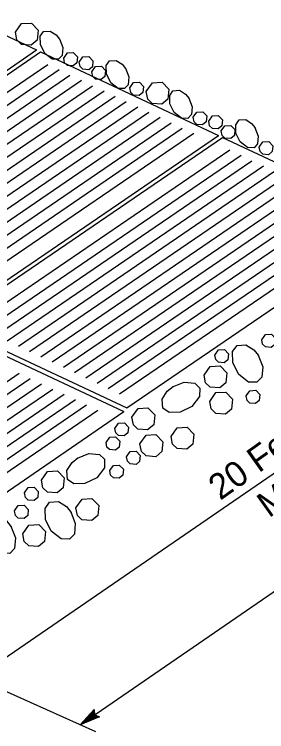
# Model space of a CAD drawing. Extents: x 6707406 to 6714471, y 1868570 to 1872341.
# Drawn here: x 6709966.5 to 6710037.9, y 1870116.6 to 1870319.2 of the extents above; entities that cross this region are included whole.
import ezdxf

# ---------------------------------------------------------------- set-up
doc = ezdxf.new("R2010")
doc.units = 0
for name, color, linetype in [('56 Stg 3 Anno', 7, 'Continuous'), ('57 Undefined', 7, 'Continuous'), ('60 Nongeo Data', 7, 'Continuous')]:
    doc.layers.add(name, color=color, linetype=linetype)

msp = doc.modelspace()

# ---------------------------------------------------------------- linework, layer by layer
at = {"layer": '56 Stg 3 Anno'}
for p, q in [((6709960.88, 1870135.33), (6710117.29, 1870242.71)), ((6709985.07, 1870118.55), (6710151.91, 1870233.1)), ((6709932.78, 1870142.01), (6709989.45, 1870116.59)), ((6709985.07, 1870118.55), (6709989.1, 1870122.86)), ((6709986.17, 1870119.31), (6709989.1, 1870122.45)), ((6709987.26, 1870120.05), (6709989.15, 1870122.08)), ((6709988.35, 1870120.8), (6709989.16, 1870121.67)), ((6709989.1, 1870122.86), (6709989.1, 1870122.86)), ((6709989.1, 1870122.86), (6709989.18, 1870121.38)), ((6709990.55, 1870120.75), (6709985.07, 1870118.55)), ((6709990.18, 1870120.92), (6709986.16, 1870119.3)), ((6709989.8, 1870121.07), (6709987.26, 1870120.05)), ((6709989.47, 1870121.25), (6709988.35, 1870120.8)), ((6709989.18, 1870121.38), (6709990.55, 1870120.75)), ((6709990.55, 1870120.75), (6709990.55, 1870120.75)), ((6709985.07, 1870118.55), (6709985.07, 1870118.55))]:
    msp.add_line(p, q, dxfattribs=at)
at = {"layer": '60 Nongeo Data'}
for p, q in [((6709933.89, 1870327.37), (6709972.77, 1870309.11)), ((6709895.36, 1870256.35), (6709972.77, 1870309.11)), ((6709896.53, 1870255.81), (6709973.94, 1870308.57)), ((6709973.94, 1870308.57), (6710024.25, 1870284.94)), ((6709903.43, 1870255.63), (6709975.95, 1870305.05)), ((6709906.61, 1870254.14), (6709979.18, 1870303.59)), ((6709909.79, 1870252.64), (6709982.23, 1870302.01)), ((6709912.98, 1870251.15), (6709985.49, 1870300.57)), ((6709916.16, 1870249.65), (6709988.6, 1870299.03)), ((6709919.34, 1870248.16), (6709991.87, 1870297.59)), ((6709922.52, 1870246.67), (6709995.05, 1870296.1)), ((6709925.7, 1870245.17), (6709998.17, 1870294.57)), ((6709928.88, 1870243.68), (6710001.39, 1870293.1)), ((6709932.06, 1870242.19), (6710004.53, 1870291.58)), ((6709935.24, 1870240.69), (6710007.74, 1870290.1)), ((6709938.43, 1870239.2), (6710010.88, 1870288.58)), ((6709941.61, 1870237.7), (6710013.99, 1870287.04)), ((6709944.79, 1870236.21), (6710017.28, 1870285.62)), ((6709946.84, 1870232.18), (6710024.25, 1870284.94)), ((6709948.01, 1870231.63), (6710025.41, 1870284.39)), ((6710025.41, 1870284.39), (6710075.72, 1870260.77)), ((6709954.91, 1870231.46), (6710027.42, 1870280.88)), ((6709958.09, 1870229.96), (6710030.66, 1870279.42)), ((6709961.27, 1870228.47), (6710033.7, 1870277.84)), ((6709964.45, 1870226.98), (6710036.97, 1870276.4)), ((6709967.63, 1870225.48), (6710040.08, 1870274.86)), ((6709970.82, 1870223.99), (6710043.34, 1870273.42)), ((6709974, 1870222.49), (6710046.53, 1870271.93)), ((6709977.18, 1870221), (6710049.65, 1870270.4)), ((6709980.36, 1870219.51), (6710052.87, 1870268.93)), ((6709983.54, 1870218.01), (6710056.01, 1870267.4)), ((6709986.72, 1870216.52), (6710059.22, 1870265.93)), ((6709989.9, 1870215.03), (6710062.35, 1870264.41)), ((6709993.08, 1870213.53), (6710065.47, 1870262.87)), ((6709996.27, 1870212.04), (6710068.76, 1870261.45)), ((6709998.31, 1870208.01), (6710075.72, 1870260.77)), ((6709948.01, 1870231.63), (6709998.31, 1870208.01)), ((6709947.18, 1870230.6), (6709997.49, 1870206.98)), ((6709895.17, 1870168.3), (6709967.84, 1870217.83)), ((6709898.35, 1870166.8), (6709971.02, 1870216.34)), ((6709901.53, 1870165.31), (6709974.21, 1870214.84)), ((6709904.71, 1870163.82), (6709977.39, 1870213.35)), ((6709907.89, 1870162.32), (6709980.57, 1870211.86)), ((6709911.07, 1870160.83), (6709983.75, 1870210.36)), ((6709914.25, 1870159.33), (6709986.93, 1870208.87)), ((6709917.44, 1870157.84), (6709990.11, 1870207.37)), ((6709919.56, 1870153.86), (6709997.49, 1870206.98))]:
    msp.add_line(p, q, dxfattribs=at)
for points in [[(6709966.8, 1870314.1), (6709968.54, 1870316.57), (6709971.31, 1870316.73), (6709973.24, 1870314.73), (6709972.96, 1870311.92), (6709971.25, 1870310.5), (6709968.51, 1870310.7), (6709967.22, 1870311.95), (6709966.8, 1870314.1)], [(6709979.24, 1870312.24), (6709980.21, 1870309.8), (6709980.01, 1870307.56), (6709979, 1870306.49), (6709977.18, 1870306.52), (6709975.11, 1870308.14), (6709973.86, 1870310.64), (6709973.82, 1870313), (6709974.76, 1870314.32), (6709976.64, 1870314.45), (6709978.32, 1870313.37), (6709979.3, 1870312.14)], [(6709980.47, 1870306.8), (6709981.51, 1870308.28), (6709983.18, 1870308.37), (6709984.34, 1870307.17), (6709984.17, 1870305.49), (6709983.14, 1870304.64), (6709981.5, 1870304.75), (6709980.72, 1870305.5), (6709980.47, 1870306.8)], [(6709984.87, 1870305.71), (6709985.91, 1870307.19), (6709987.58, 1870307.29), (6709988.74, 1870306.09), (6709988.57, 1870304.4), (6709987.54, 1870303.55), (6709985.9, 1870303.67), (6709985.12, 1870304.42), (6709984.87, 1870305.71)], [(6709997.92, 1870303.95), (6709998.88, 1870301.51), (6709998.69, 1870299.27), (6709997.68, 1870298.21), (6709995.86, 1870298.24), (6709993.79, 1870299.86), (6709992.54, 1870302.36), (6709992.5, 1870304.71), (6709993.44, 1870306.04), (6709995.32, 1870306.16), (6709997, 1870305.09), (6709997.98, 1870303.86)], [(6709988.41, 1870302.94), (6709989.46, 1870304.43), (6709991.12, 1870304.52), (6709992.28, 1870303.32), (6709992.11, 1870301.64), (6709991.08, 1870300.78), (6709989.44, 1870300.9), (6709988.67, 1870301.65), (6709988.41, 1870302.94)], [(6709999.15, 1870298.4), (6710000.19, 1870299.89), (6710001.86, 1870299.98), (6710003.02, 1870298.78), (6710002.85, 1870297.1), (6710001.82, 1870296.24), (6710000.18, 1870296.36), (6709999.4, 1870297.11), (6709999.15, 1870298.4)], [(6710003.79, 1870297.4), (6710005.53, 1870299.87), (6710008.3, 1870300.03), (6710010.23, 1870298.03), (6710009.95, 1870295.22), (6710008.24, 1870293.8), (6710005.5, 1870294), (6710004.21, 1870295.25), (6710003.79, 1870297.4)], [(6710015.85, 1870295.54), (6710016.82, 1870293.1), (6710016.62, 1870290.86), (6710015.61, 1870289.79), (6710013.79, 1870289.82), (6710011.72, 1870291.44), (6710010.47, 1870293.94), (6710010.43, 1870296.3), (6710011.37, 1870297.62), (6710013.25, 1870297.75), (6710014.93, 1870296.67), (6710015.91, 1870295.44)], [(6710017.08, 1870290.1), (6710018.12, 1870291.58), (6710019.79, 1870291.67), (6710020.95, 1870290.47), (6710020.78, 1870288.79), (6710019.75, 1870287.94), (6710018.11, 1870288.05), (6710017.33, 1870288.8), (6710017.08, 1870290.1)], [(6710021.48, 1870289.01), (6710022.53, 1870290.49), (6710024.19, 1870290.59), (6710025.35, 1870289.39), (6710025.18, 1870287.7), (6710024.15, 1870286.85), (6710022.51, 1870286.97), (6710021.73, 1870287.72), (6710021.48, 1870289.01)], [(6710025.02, 1870286.24), (6710026.07, 1870287.73), (6710027.73, 1870287.82), (6710028.89, 1870286.62), (6710028.72, 1870284.94), (6710027.69, 1870284.08), (6710026.05, 1870284.2), (6710025.28, 1870284.95), (6710025.02, 1870286.24)], [(6710034.53, 1870287.25), (6710035.5, 1870284.81), (6710035.3, 1870282.57), (6710034.29, 1870281.51), (6710032.47, 1870281.54), (6710030.4, 1870283.16), (6710029.15, 1870285.66), (6710029.11, 1870288.01), (6710030.05, 1870289.34), (6710031.93, 1870289.46), (6710033.61, 1870288.39), (6710034.59, 1870287.16)], [(6710035.76, 1870281.7), (6710036.8, 1870283.19), (6710038.47, 1870283.28), (6710039.63, 1870282.08), (6710039.46, 1870280.4), (6710038.43, 1870279.54), (6710036.79, 1870279.66), (6710036.01, 1870280.41), (6710035.76, 1870281.7)], [(6710036.48, 1870227.27), (6710037.53, 1870228.76), (6710039.19, 1870228.85), (6710040.35, 1870227.65), (6710040.18, 1870225.97), (6710039.15, 1870225.11), (6710037.51, 1870225.23), (6710036.73, 1870225.98), (6710036.48, 1870227.27)], [(6710035.45, 1870222.91), (6710036.74, 1870219.66), (6710036.48, 1870216.67), (6710035.13, 1870215.25), (6710032.7, 1870215.29), (6710029.95, 1870217.45), (6710028.28, 1870220.78), (6710028.22, 1870223.92), (6710029.48, 1870225.69), (6710031.98, 1870225.86), (6710034.22, 1870224.42), (6710035.53, 1870222.78)], [(6710023.22, 1870222.95), (6710024.27, 1870224.43), (6710025.93, 1870224.53), (6710027.09, 1870223.33), (6710026.92, 1870221.64), (6710025.89, 1870220.79), (6710024.25, 1870220.91), (6710023.48, 1870221.66), (6710023.22, 1870222.95)], [(6710020.15, 1870217.28), (6710021.89, 1870219.76), (6710024.67, 1870219.92), (6710026.6, 1870217.91), (6710026.32, 1870215.11), (6710024.6, 1870213.68), (6710021.86, 1870213.88), (6710020.57, 1870215.13), (6710020.15, 1870217.28)], [(6710011.27, 1870213.96), (6710014.52, 1870215.25), (6710017.51, 1870214.99), (6710018.93, 1870213.64), (6710018.89, 1870211.22), (6710016.73, 1870208.46), (6710013.4, 1870206.79), (6710010.26, 1870206.74), (6710008.49, 1870207.99), (6710008.32, 1870210.5), (6710009.76, 1870212.73), (6710011.4, 1870214.04)], [(6710032.06, 1870211.41), (6710033.11, 1870212.89), (6710034.77, 1870212.99), (6710035.93, 1870211.78), (6710035.76, 1870210.1), (6710034.74, 1870209.25), (6710033.09, 1870209.37), (6710032.31, 1870210.12), (6710032.06, 1870211.41)], [(6710021.79, 1870209.88), (6710023.53, 1870212.35), (6710026.3, 1870212.51), (6710028.23, 1870210.51), (6710027.95, 1870207.7), (6710026.24, 1870206.28), (6710023.5, 1870206.47), (6710022.21, 1870207.73), (6710021.79, 1870209.88)], [(6709999.74, 1870205.43), (6710001.48, 1870207.9), (6710004.26, 1870208.06), (6710006.19, 1870206.06), (6710005.91, 1870203.26), (6710004.2, 1870201.83), (6710001.45, 1870202.03), (6710000.16, 1870203.28), (6709999.75, 1870205.43)], [(6709994.92, 1870202.25), (6709995.96, 1870203.74), (6709997.63, 1870203.84), (6709998.79, 1870202.63), (6709998.62, 1870200.95), (6709997.59, 1870200.09), (6709995.95, 1870200.21), (6709995.17, 1870200.97), (6709994.92, 1870202.25)], [(6710010.85, 1870199.95), (6710012.59, 1870202.42), (6710015.37, 1870202.58), (6710017.3, 1870200.58), (6710017.02, 1870197.77), (6710015.31, 1870196.35), (6710012.56, 1870196.54), (6710011.27, 1870197.79), (6710010.86, 1870199.95)], [(6709992.43, 1870198.27), (6709993.47, 1870199.75), (6709995.14, 1870199.85), (6709996.3, 1870198.65), (6709996.13, 1870196.96), (6709995.1, 1870196.11), (6709993.45, 1870196.23), (6709992.68, 1870196.98), (6709992.43, 1870198.27)], [(6710002.03, 1870197.85), (6710003.77, 1870200.33), (6710006.55, 1870200.49), (6710008.48, 1870198.48), (6710008.2, 1870195.68), (6710006.49, 1870194.25), (6710003.74, 1870194.45), (6710002.45, 1870195.7), (6710002.03, 1870197.85)], [(6709984.34, 1870193.82), (6709987.59, 1870195.11), (6709990.58, 1870194.85), (6709992, 1870193.5), (6709991.96, 1870191.07), (6709989.8, 1870188.32), (6709986.47, 1870186.65), (6709983.33, 1870186.59), (6709981.56, 1870187.85), (6709981.39, 1870190.35), (6709982.83, 1870192.59), (6709984.47, 1870193.9)], [(6709998.24, 1870194.23), (6709999.29, 1870195.72), (6710000.95, 1870195.81), (6710002.11, 1870194.61), (6710001.94, 1870192.93), (6710000.91, 1870192.07), (6709999.27, 1870192.19), (6709998.49, 1870192.94), (6709998.24, 1870194.23)], [(6709993.47, 1870190.3), (6709994.52, 1870191.78), (6709996.18, 1870191.88), (6709997.34, 1870190.68), (6709997.18, 1870188.99), (6709996.15, 1870188.14), (6709994.5, 1870188.26), (6709993.73, 1870189.01), (6709993.48, 1870190.3)], [(6709974.15, 1870187.6), (6709975.89, 1870190.08), (6709978.66, 1870190.24), (6709980.6, 1870188.23), (6709980.32, 1870185.43), (6709978.6, 1870184), (6709975.86, 1870184.2), (6709974.57, 1870185.45), (6709974.15, 1870187.6)], [(6709969.4, 1870184.05), (6709970.44, 1870185.53), (6709972.11, 1870185.63), (6709973.27, 1870184.43), (6709973.1, 1870182.75), (6709972.07, 1870181.89), (6709970.42, 1870182.01), (6709969.65, 1870182.76), (6709969.4, 1870184.05)], [(6709983.92, 1870179.8), (6709985.66, 1870182.28), (6709988.44, 1870182.43), (6709990.37, 1870180.43), (6709990.09, 1870177.63), (6709988.38, 1870176.2), (6709985.63, 1870176.4), (6709984.34, 1870177.65), (6709983.92, 1870179.8)], [(6709966.58, 1870178.94), (6709967.62, 1870180.43), (6709969.29, 1870180.52), (6709970.45, 1870179.32), (6709970.28, 1870177.64), (6709969.25, 1870176.78), (6709967.61, 1870176.9), (6709966.83, 1870177.65), (6709966.58, 1870178.94)], [(6709982.45, 1870178.63), (6709983.74, 1870175.38), (6709983.48, 1870172.39), (6709982.13, 1870170.97), (6709979.71, 1870171.01), (6709976.95, 1870173.17), (6709975.28, 1870176.5), (6709975.23, 1870179.64), (6709976.48, 1870181.41), (6709978.99, 1870181.58), (6709981.22, 1870180.14), (6709982.53, 1870178.5)], [(6709965.54, 1870174.58), (6709966.83, 1870171.33), (6709966.57, 1870168.34), (6709965.22, 1870166.92), (6709962.8, 1870166.96), (6709960.04, 1870169.12), (6709958.38, 1870172.45), (6709958.32, 1870175.59), (6709959.58, 1870177.36), (6709962.08, 1870177.53), (6709964.32, 1870176.09), (6709965.63, 1870174.45)], [(6709968.87, 1870172.45), (6709970.61, 1870174.93), (6709973.38, 1870175.09), (6709975.31, 1870173.08), (6709975.03, 1870170.28), (6709973.32, 1870168.85), (6709970.58, 1870169.05), (6709969.29, 1870170.3), (6709968.87, 1870172.45)]]:
    msp.add_lwpolyline(points, dxfattribs=at)

# ---------------------------------------------------------------- texts
at = {"layer": '57 Undefined'}
for s, p in [('20 Feet', (6710024.73, 1870181.74)), ('Min', (6710038.5, 1870176.81))]:
    msp.add_text(s, height=7.2, rotation=35.4657, dxfattribs=at).set_placement(p)

doc.saveas('drawing.dxf')
